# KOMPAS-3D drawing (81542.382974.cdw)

Referenced files in F:\Моё,не трогать\Автоклав\: Ерш.cdw
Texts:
  Ерш для шарового
  крана
  материал:
  Нержа,Латунь,Бронза
  Шестигранник
Dimensions and other numbers on the sheet: 1 Штука; 6; 8; 12; 26; 10; 17; 1/4 Трубная; 1:1; 1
